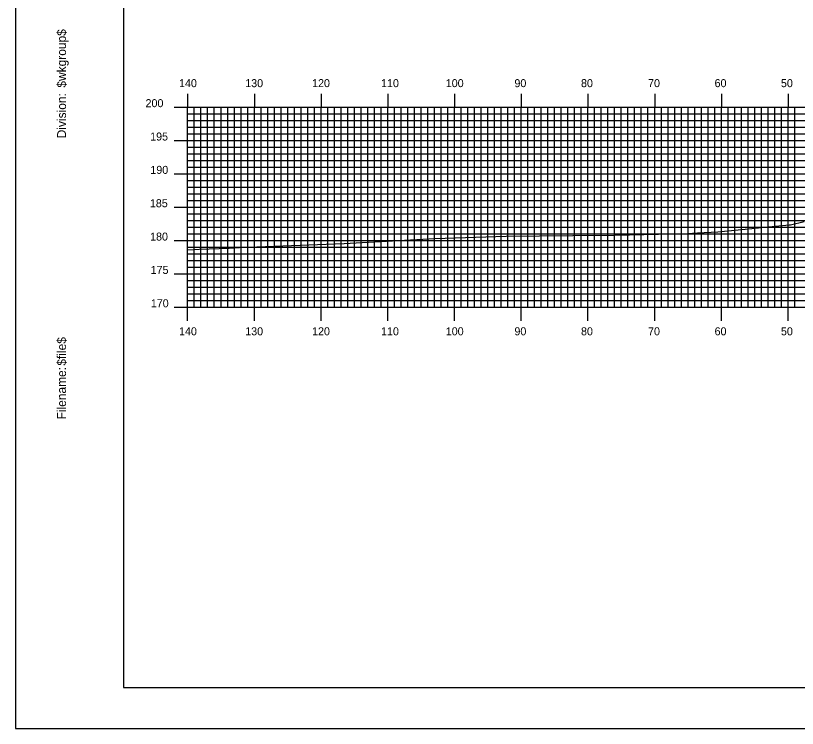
# Model space of a CAD drawing. Extents: x 1824360 to 1824703, y 442591 to 442811.
# Drawn here: x 1824359.5 to 1824476.7, y 442590.5 to 442697.4 of the extents above; entities that cross this region are included whole.
import ezdxf

# ---------------------------------------------------------------- set-up
doc = ezdxf.new("R2010")
doc.units = 0
for name, color, linetype in [('BORDER', 7, 'Continuous'), ('H_V ANNOTATION', 7, 'Continuous'), ('MAJOR', 7, 'Continuous'), ('MINOR', 7, 'Continuous'), ('PLOT BOUNDARY', 7, 'Continuous'), ('S_Roadway_Centerline', 7, 'Continuous')]:
    doc.layers.add(name, color=color, linetype=linetype)

msp = doc.modelspace()

# ---------------------------------------------------------------- linework, layer by layer
at = {"layer": 'BORDER'}
msp.add_lwpolyline([(1824375.73, 442596.67), (1824695.73, 442596.67), (1824695.73, 442806.67), (1824375.73, 442806.67)], close=True, dxfattribs=at)
at = {"layer": 'MAJOR'}
for p, q in [((1824385.33, 442685.67), (1824385.33, 442683.67)), ((1824395.33, 442685.67), (1824395.33, 442683.67)), ((1824405.33, 442685.67), (1824405.33, 442683.67)), ((1824415.33, 442685.67), (1824415.33, 442683.67)), ((1824425.33, 442685.67), (1824425.33, 442683.67)), ((1824435.33, 442685.67), (1824435.33, 442683.67)), ((1824445.33, 442685.67), (1824445.33, 442683.67)), ((1824455.33, 442685.67), (1824455.33, 442683.67)), ((1824465.33, 442685.67), (1824465.33, 442683.67)), ((1824475.33, 442685.67), (1824475.33, 442683.67)), ((1824383.33, 442683.67), (1824385.33, 442683.67)), ((1824385.33, 442683.67), (1824665.33, 442683.67)), ((1824385.33, 442653.67), (1824385.33, 442683.67)), ((1824385.33, 442653.67), (1824385.33, 442683.67)), ((1824385.33, 442683.67), (1824665.33, 442683.67)), ((1824395.33, 442653.67), (1824395.33, 442683.67)), ((1824405.33, 442653.67), (1824405.33, 442683.67)), ((1824415.33, 442653.67), (1824415.33, 442683.67)), ((1824425.33, 442653.67), (1824425.33, 442683.67)), ((1824435.33, 442653.67), (1824435.33, 442683.67)), ((1824445.33, 442653.67), (1824445.33, 442683.67)), ((1824455.33, 442653.67), (1824455.33, 442683.67)), ((1824465.33, 442653.67), (1824465.33, 442683.67)), ((1824475.33, 442653.67), (1824475.33, 442683.67)), ((1824383.33, 442678.67), (1824385.33, 442678.67)), ((1824385.33, 442678.67), (1824665.33, 442678.67)), ((1824383.33, 442673.67), (1824385.33, 442673.67)), ((1824385.33, 442673.67), (1824665.33, 442673.67)), ((1824383.33, 442668.67), (1824385.33, 442668.67)), ((1824385.33, 442668.67), (1824665.33, 442668.67)), ((1824383.33, 442663.67), (1824385.33, 442663.67)), ((1824385.33, 442663.67), (1824665.33, 442663.67)), ((1824383.33, 442658.67), (1824385.33, 442658.67)), ((1824385.33, 442658.67), (1824665.33, 442658.67)), ((1824383.33, 442653.67), (1824385.33, 442653.67)), ((1824385.33, 442653.67), (1824665.33, 442653.67)), ((1824385.33, 442653.67), (1824665.33, 442653.67)), ((1824385.33, 442651.66), (1824385.33, 442653.67)), ((1824395.33, 442651.66), (1824395.33, 442653.67)), ((1824405.33, 442651.66), (1824405.33, 442653.67)), ((1824415.33, 442651.66), (1824415.33, 442653.67)), ((1824425.33, 442651.66), (1824425.33, 442653.67)), ((1824435.33, 442651.66), (1824435.33, 442653.67)), ((1824445.33, 442651.66), (1824445.33, 442653.67)), ((1824455.33, 442651.66), (1824455.33, 442653.67)), ((1824465.33, 442651.66), (1824465.33, 442653.67)), ((1824475.33, 442651.66), (1824475.33, 442653.67))]:
    msp.add_line(p, q, dxfattribs=at)
at = {"layer": 'MINOR'}
for p, q in [((1824386.33, 442653.67), (1824386.33, 442683.67)), ((1824387.33, 442653.67), (1824387.33, 442683.67)), ((1824388.33, 442653.67), (1824388.33, 442683.67)), ((1824389.33, 442653.67), (1824389.33, 442683.67)), ((1824390.33, 442653.67), (1824390.33, 442683.67)), ((1824391.33, 442653.67), (1824391.33, 442683.67)), ((1824392.33, 442653.67), (1824392.33, 442683.67)), ((1824393.33, 442653.67), (1824393.33, 442683.67)), ((1824394.33, 442653.67), (1824394.33, 442683.67)), ((1824396.33, 442653.67), (1824396.33, 442683.67)), ((1824397.33, 442653.67), (1824397.33, 442683.67)), ((1824398.33, 442653.67), (1824398.33, 442683.67)), ((1824399.33, 442653.67), (1824399.33, 442683.67)), ((1824400.33, 442653.67), (1824400.33, 442683.67)), ((1824401.33, 442653.67), (1824401.33, 442683.67)), ((1824402.33, 442653.67), (1824402.33, 442683.67)), ((1824403.33, 442653.67), (1824403.33, 442683.67)), ((1824404.33, 442653.67), (1824404.33, 442683.67)), ((1824406.33, 442653.67), (1824406.33, 442683.67)), ((1824407.33, 442653.67), (1824407.33, 442683.67)), ((1824408.33, 442653.67), (1824408.33, 442683.67)), ((1824409.33, 442653.67), (1824409.33, 442683.67)), ((1824410.33, 442653.67), (1824410.33, 442683.67)), ((1824411.33, 442653.67), (1824411.33, 442683.67)), ((1824412.33, 442653.67), (1824412.33, 442683.67)), ((1824413.33, 442653.67), (1824413.33, 442683.67)), ((1824414.33, 442653.67), (1824414.33, 442683.67)), ((1824416.33, 442653.67), (1824416.33, 442683.67)), ((1824417.33, 442653.67), (1824417.33, 442683.67)), ((1824418.33, 442653.67), (1824418.33, 442683.67)), ((1824419.33, 442653.67), (1824419.33, 442683.67)), ((1824420.33, 442653.67), (1824420.33, 442683.67)), ((1824421.33, 442653.67), (1824421.33, 442683.67)), ((1824422.33, 442653.67), (1824422.33, 442683.67)), ((1824423.33, 442653.67), (1824423.33, 442683.67)), ((1824424.33, 442653.67), (1824424.33, 442683.67)), ((1824426.33, 442653.67), (1824426.33, 442683.67)), ((1824427.33, 442653.67), (1824427.33, 442683.67)), ((1824428.33, 442653.67), (1824428.33, 442683.67)), ((1824429.33, 442653.67), (1824429.33, 442683.67)), ((1824430.33, 442653.67), (1824430.33, 442683.67)), ((1824431.33, 442653.67), (1824431.33, 442683.67)), ((1824432.33, 442653.67), (1824432.33, 442683.67)), ((1824433.33, 442653.67), (1824433.33, 442683.67)), ((1824434.33, 442653.67), (1824434.33, 442683.67)), ((1824436.33, 442653.67), (1824436.33, 442683.67)), ((1824437.33, 442653.67), (1824437.33, 442683.67)), ((1824438.33, 442653.67), (1824438.33, 442683.67)), ((1824439.33, 442653.67), (1824439.33, 442683.67)), ((1824440.33, 442653.67), (1824440.33, 442683.67)), ((1824441.33, 442653.67), (1824441.33, 442683.67)), ((1824442.33, 442653.67), (1824442.33, 442683.67)), ((1824443.33, 442653.67), (1824443.33, 442683.67)), ((1824444.33, 442653.67), (1824444.33, 442683.67)), ((1824446.33, 442653.67), (1824446.33, 442683.67)), ((1824447.33, 442653.67), (1824447.33, 442683.67)), ((1824448.33, 442653.67), (1824448.33, 442683.67)), ((1824449.33, 442653.67), (1824449.33, 442683.67)), ((1824450.33, 442653.67), (1824450.33, 442683.67)), ((1824451.33, 442653.67), (1824451.33, 442683.67)), ((1824452.33, 442653.67), (1824452.33, 442683.67)), ((1824453.33, 442653.67), (1824453.33, 442683.67)), ((1824454.33, 442653.67), (1824454.33, 442683.67)), ((1824456.33, 442653.67), (1824456.33, 442683.67)), ((1824457.33, 442653.67), (1824457.33, 442683.67)), ((1824458.33, 442653.67), (1824458.33, 442683.67)), ((1824459.33, 442653.67), (1824459.33, 442683.67)), ((1824460.33, 442653.67), (1824460.33, 442683.67)), ((1824461.33, 442653.67), (1824461.33, 442683.67)), ((1824462.33, 442653.67), (1824462.33, 442683.67)), ((1824463.33, 442653.67), (1824463.33, 442683.67)), ((1824464.33, 442653.67), (1824464.33, 442683.67)), ((1824466.33, 442653.67), (1824466.33, 442683.67)), ((1824467.33, 442653.67), (1824467.33, 442683.67)), ((1824468.33, 442653.67), (1824468.33, 442683.67)), ((1824469.33, 442653.67), (1824469.33, 442683.67)), ((1824470.33, 442653.67), (1824470.33, 442683.67)), ((1824471.33, 442653.67), (1824471.33, 442683.67)), ((1824472.33, 442653.67), (1824472.33, 442683.67)), ((1824473.33, 442653.67), (1824473.33, 442683.67)), ((1824474.33, 442653.67), (1824474.33, 442683.67)), ((1824476.33, 442653.67), (1824476.33, 442683.67)), ((1824385.33, 442682.67), (1824665.33, 442682.67)), ((1824385.33, 442682.67), (1824387.34, 442682.67)), ((1824385.33, 442681.67), (1824665.33, 442681.67)), ((1824385.33, 442681.67), (1824387.34, 442681.67)), ((1824385.33, 442680.67), (1824665.33, 442680.67)), ((1824385.33, 442680.67), (1824387.34, 442680.67)), ((1824385.33, 442679.67), (1824665.33, 442679.67)), ((1824385.33, 442679.67), (1824387.34, 442679.67)), ((1824385.33, 442677.67), (1824665.33, 442677.67)), ((1824385.33, 442677.67), (1824387.34, 442677.67)), ((1824385.33, 442676.67), (1824665.33, 442676.67)), ((1824385.33, 442676.67), (1824387.34, 442676.67)), ((1824385.33, 442675.67), (1824665.33, 442675.67)), ((1824385.33, 442675.67), (1824387.34, 442675.67)), ((1824385.33, 442674.67), (1824665.33, 442674.67)), ((1824385.33, 442674.67), (1824387.34, 442674.67)), ((1824385.33, 442672.67), (1824665.33, 442672.67)), ((1824385.33, 442672.67), (1824387.34, 442672.67)), ((1824385.33, 442671.67), (1824665.33, 442671.67)), ((1824385.33, 442671.67), (1824387.34, 442671.67)), ((1824385.33, 442670.67), (1824665.33, 442670.67)), ((1824385.33, 442670.67), (1824387.34, 442670.67)), ((1824385.33, 442669.67), (1824665.33, 442669.67)), ((1824385.33, 442669.67), (1824387.34, 442669.67)), ((1824385.33, 442667.67), (1824665.33, 442667.67)), ((1824385.33, 442667.67), (1824387.34, 442667.67)), ((1824385.33, 442666.67), (1824665.33, 442666.67)), ((1824385.33, 442666.67), (1824387.34, 442666.67)), ((1824385.33, 442665.67), (1824665.33, 442665.67)), ((1824385.33, 442665.67), (1824387.34, 442665.67)), ((1824385.33, 442664.67), (1824665.33, 442664.67)), ((1824385.33, 442664.67), (1824387.34, 442664.67)), ((1824385.33, 442662.67), (1824665.33, 442662.67)), ((1824385.33, 442662.67), (1824387.34, 442662.67)), ((1824385.33, 442661.67), (1824665.33, 442661.67)), ((1824385.33, 442661.67), (1824387.34, 442661.67)), ((1824385.33, 442660.67), (1824665.33, 442660.67)), ((1824385.33, 442660.67), (1824387.34, 442660.67)), ((1824385.33, 442659.67), (1824665.33, 442659.67)), ((1824385.33, 442659.67), (1824387.34, 442659.67)), ((1824385.33, 442657.67), (1824665.33, 442657.67)), ((1824385.33, 442657.67), (1824387.34, 442657.67)), ((1824385.33, 442656.67), (1824665.33, 442656.67)), ((1824385.33, 442656.67), (1824387.34, 442656.67)), ((1824385.33, 442655.67), (1824665.33, 442655.67)), ((1824385.33, 442655.67), (1824387.34, 442655.67)), ((1824385.33, 442654.67), (1824665.33, 442654.67)), ((1824385.33, 442654.67), (1824387.34, 442654.67))]:
    msp.add_line(p, q, dxfattribs=at)
at = {"layer": 'PLOT BOUNDARY'}
msp.add_lwpolyline([(1824359.55, 442590.55), (1824699.55, 442590.55), (1824699.55, 442810.55), (1824359.55, 442810.55)], close=True, dxfattribs=at)
at = {"layer": 'S_Roadway_Centerline'}
msp.add_lwpolyline([(1824385.33, 442662.27), (1824387.04, 442662.39), (1824391.56, 442662.54), (1824393.11, 442662.65), (1824406.09, 442663.12), (1824408.79, 442663.21), (1824422.39, 442664), (1824433.09, 442664.32), (1824443.08, 442664.44), (1824449.38, 442664.49), (1824460.23, 442664.73), (1824461.74, 442664.82), (1824464.79, 442664.99), (1824475.51, 442666.03), (1824475.63, 442666.03), (1824475.71, 442666.05), (1824477.74, 442666.54)], dxfattribs=at)

# ---------------------------------------------------------------- texts
at = {"layer": 'BORDER'}
for s, p in [('$wkgroup$', (1824367.1, 442686.6)), ('Division:', (1824367.1, 442679)), ('$file$', (1824367.1, 442644.92)), ('Filename:', (1824367.1, 442636.86))]:
    msp.add_text(s, height=1.339, rotation=90, dxfattribs=at).set_placement(p)
at = {"layer": 'H_V ANNOTATION'}
for s, p in [('140', (1824384.04, 442686.67)), ('130', (1824393.96, 442686.67)), ('120', (1824403.98, 442686.67)), ('110', (1824414.32, 442686.67)), ('100', (1824424.02, 442686.67)), ('90', (1824434.31, 442686.67)), ('80', (1824444.29, 442686.67)), ('70', (1824454.34, 442686.67)), ('60', (1824464.31, 442686.67)), ('50', (1824474.26, 442686.67)), ('200', (1824379.02, 442683.67)), ('195', (1824379.71, 442678.67)), ('190', (1824379.74, 442673.67)), ('185', (1824379.67, 442668.67)), ('180', (1824379.7, 442663.67)), ('175', (1824379.78, 442658.67)), ('170', (1824379.81, 442653.67)), ('140', (1824384.04, 442649.47)), ('130', (1824393.96, 442649.47)), ('120', (1824403.98, 442649.47)), ('110', (1824414.32, 442649.47)), ('100', (1824424.02, 442649.47)), ('90', (1824434.31, 442649.47)), ('80', (1824444.29, 442649.47)), ('70', (1824454.34, 442649.47)), ('60', (1824464.31, 442649.47)), ('50', (1824474.26, 442649.47))]:
    msp.add_text(s, height=1.2, dxfattribs=at).set_placement(p)
at = {"layer": 'MAJOR'}
msp.add_text('-', height=0.012, dxfattribs=at).set_placement((1824385.33, 442653.67))

doc.saveas('drawing.dxf')
